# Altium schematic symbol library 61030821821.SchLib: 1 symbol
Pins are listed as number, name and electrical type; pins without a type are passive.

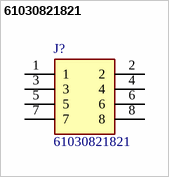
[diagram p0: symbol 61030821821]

## 61030821821
designator J?
WURTH ELEKTRONIK - 61030821821 - PCB Receptacle, Board-to-Board, 2.54 mm, 2 Rows, 8 Contacts, Surface Mount, WR-PHD Series; Geometry.Height: 7.75mm
footprint 61030821821
pins: 1, 2, 3, 4, 5, 6, 7, 8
